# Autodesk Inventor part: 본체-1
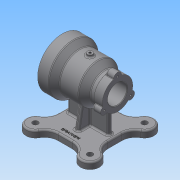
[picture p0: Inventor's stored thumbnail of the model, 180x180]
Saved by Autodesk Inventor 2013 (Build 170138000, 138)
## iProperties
Created: 2017-03
Part Number: 본체-1
Material: 일반
Document SubType Name: Modeling
Designer: Administrator
Density: 1 g/cm^3
Mass: 365.909 g
Surface Area: 842.375 cm^2
Volume: 365.909 cm^3
Author: Administrator
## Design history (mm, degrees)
sketch "스케치1"
  geometry: L1 (-50, 0)-(50, 0); L2 (-50, 35)-(-27, 35); L3 (-27, 35)-(-27, 26); L4 (-27, 26)-(20, 26); L5 (20, 26)-(20, 17.5); L6 (20, 17.5)-(50, 17.5); L7 (50, 17.5)-(50, 27.5); L8 (50, 27.5)-(35, 27.5); L9 (15, 36)-(-19, 36); L10 (-19, 36)-(-30, 45); L11 (-30, 45)-(-50, 45); L12 (-50, 45)-(-50, 35); L13 (15, 36)-(27, 26.182); L14 (27, 26.182)-(35, 26.182); L15 (35, 26.182)-(35, 27.5); 2 further points
  constraints: 30 end point, 9 parallel, 3 perpendicular, 2 vertical alignment, 1 coincident, 1 horizontal, 1 midpoint, 1 vertical
  dimensions: "d0" = 100 distance of L1.start L1.end; "d2" = 20 distance of L10.end L11.end; "d3" = 31 distance from line of L9.end L12; "d6" = 65 distance from line of L9.start L12; "d8" = 70 diameter of L2 L1; "d9" = 52 diameter of L4 L1; "d10" = 35 diameter of L6 L1; "d11" = 23 distance of L2.start L2.end; "d12" = 47 distance of L3.end L4.end; "d13" = 90 diameter of L11 L1; "d17" = 55 diameter of L8 L1; "d18" = 72 diameter of L9 L1; "d19" = 23 distance from line of L13.end L7; "d20" = 15 distance of L7.end L8.end
revolve "회전1" sketch "스케치1" stored, may be unused: angle "d21" = 90 deg
node "작업 평면1"
sketch "스케치2"
  geometry: L1 (-45, 45)-(45, 45); L2 (45, 45)-(45, -45); L3 (45, -45)-(-45, -45); L4 (-45, -45)-(-45, 45); L5 (-45, 45)-(45, -45); L6 (45, 45)-(-45, -45); L7 (-45, -33.103)-(-45, 33.103); L8 (45, 33.103)-(45, -33.103); L9 (-33.103, 45)-(33.103, 45); L10 (-33.103, -45)-(33.103, -45); A1 r 70 centre (0, 0) between (-49.497, 49.497) and (49.497, 49.497); A2 r 17 centre (-49.497, 49.497) between (-45, 33.103) and (-33.103, 45); A3 r 17 centre (49.497, 49.497) between (45, 33.103) and (33.103, 45); A4 r 17 centre (-49.497, -49.497) between (-45, -33.103) and (-33.103, -45); A5 r 17 centre (49.497, -49.497) between (45, -33.103) and (33.103, -45); 3 further points
  constraints: 20 end point, 12 point on circle, 8 point on line, 5 centre point, 5 coincident, 3 equal radius, 2 horizontal alignment, 2 midpoint, 2 parallel, 2 perpendicular, 2 vertical alignment, 1 horizontal
  dimensions: "d23" = 140 diameter of A1; "d26" = 90 distance of L1.start L1.end; "d27" = 90 deg dimension on point (0, 0) A1.start point (-49.497, -49.497); "d28" = 34 diameter of A2
extrude "돌출1" join sketch "스케치2" distance "d29" = 12; taper "d30" = 0 deg
fillet "모깎기1" dims "d35" = 25
node "작업 평면2"
sketch "스케치5"
  geometry: C1 r 5 at (0, 0); 1 further point
  constraints: 1 centre point, 1 coincident
  dimensions: "d37" = 10 diameter of C1
extrude "돌출2" join sketch "스케치5" stored distance "d39" = 74; taper "d40" = 0 deg
sketch "스케치6"
  geometry: C1 r 5 at (0, 0) reference; 1 further point
  constraints: 1 coincident
hole "구멍1" sketch "스케치6" at (0, 0) diameter "d41" = 4.134; stored, may be unused: countersink angle "d45" = 90 deg, drill point angle "d47" = 118 deg; dims "d42" = 6, "d43" = 4, "d44" = 2, "d46" = 8
sketch "스케치8"
  geometry: C1 r 5 at (-49.497, 49.497); C2 r 5 at (49.497, 49.497); C3 r 5 at (-49.497, -49.497); C4 r 5 at (49.497, -49.497); A1 r 17 centre (-49.497, 49.497) between (-34.661, 57.796) and (-57.796, 34.661) reference; A2 r 17 centre (-49.497, -49.497) between (-57.796, -34.661) and (-34.661, -57.796) reference; A3 r 17 centre (49.497, -49.497) between (34.661, -57.796) and (57.796, -34.661) reference; A4 r 17 centre (49.497, 49.497) between (57.796, 34.661) and (34.661, 57.796) reference; 1 further point
  constraints: 4 centre point, 4 coincident, 3 equal radius
  dimensions: "d60" = 10 diameter of C1
extrude "돌출3" cut sketch "스케치8" stored distance "d62" = 74; taper "d63" = 0 deg
sketch "스케치9"
  geometry: C1 r 17.5 at (0, 0) reference; A1 r 27.5 centre (0, 0) between (-27.5, 0) and (-26.609, -6.943) reference; A2 r 7 centre (-27.5, 0) between (-26.609, 6.943) and (-26.609, -6.943)
  constraints: 5 point on circle, 1 centre point, 1 horizontal alignment
  dimensions: "d64" = 14 diameter of A2
extrude "돌출4" join sketch "스케치9" distance "d66" = 15; taper "d67" = 0 deg
sketch "스케치10"
  geometry: A1 r 7 centre (0, 0) between (0.891, 6.943) and (0.891, -6.943) reference; 1 further point
  constraints: 1 coincident
hole "구멍3" sketch "스케치10" at (0, 0) diameter "d68" = 3.242; stored, may be unused: countersink angle "d72" = 90 deg, drill point angle "d74" = 118 deg; dims "d69" = 9, "d70" = 4, "d71" = 2, "d73" = 11
sketch "스케치11"
  geometry: L1 (12.842, -70)-(-12.842, -70) reference; L2 (-12.842, -70)-(-34.661, -70) reference; L3 (-34.661, -70)-(-66.497, -70) reference; L4 (34.661, -70)-(12.842, -70) reference; L5 (66.497, -70)-(34.661, -70) reference; L6 (-18.14, -31.096)-(-25, -70); L7 (0, 0)-(0, -70); L8 (0, -36)-(0, -70); A1 r 36 centre (0, 0) between (-18.14, -31.096) and (0, -36) reference; 3 further points
  constraints: 6 end point, 2 point on circle, 2 point on line, 1 collinear, 1 midpoint
  dimensions: "d78" = 100 deg angle of L6 L3; "d79" = 25 horizontal distance of L6.end point (0, 0)
extrude "돌출5" join sketch "스케치11" stored distance "d80" = 8; taper "d81" = 0 deg
chamfer "모따기1" distance "d86" = 1; stored, may be unused: second distance "d87" = 2, angle "d88" = 45 deg
fillet "모깎기3" dims "d89" = 3
sketch "스케치13"
  geometry: L1 (29.226, -44.367)-(19.774, -36.633) reference; L2 (18, -36)-(-14, -36) reference; L3 (4, -70)-(4, -31.096) reference; L4 (19.774, -36.633)-(18, -36) reference; L5 (50, -45)-(31, -45) reference; L6 (37.279, -70)-(12.842, -70) reference; L7 (37.279, -70)-(63.497, -70) reference; L8 (31, -45)-(29.226, -44.367) reference; L9 (37, -45)-(37, -70); 2 further points
  constraints: 2 end point, 2 point on line, 1 vertical
  dimensions: "d94" = 37 distance from line of L9 point (0, 0)
feature "리브1" sketch "스케치13" dims "d95" = 1, "d96" = 8, "d97" = 0, "d98" = 0, "d99" = 1, "d100" = 1
fillet "모깎기4" dims "d101" = 3
fillet "모깎기5" dims "d102" = 3
fillet "모깎기6" dims "d103" = 3
sketch "스케치14" dims "d104" = 80
  geometry: C1 r 36 at (0, 0) reference; 1 further point
  constraints: 2 horizontal alignment, 2 other
hole "구멍4" sketch "스케치14" at (40, 0) diameter "d106" = 3.242; stored, may be unused: countersink angle "d110" = 90 deg, drill point angle "d112" = 118 deg; dims "d107" = 9, "d108" = 4, "d109" = 2, "d111" = 11
fillet "모깎기7" dims "d116" = 3
fillet "모깎기8" dims "d117" = 1, "d118" = 3
fillet "모깎기9" dims "d119" = 3
sketch "스케치15"
  geometry: L1 (45, -12.842)-(45, 12.842) reference; 2 further points
  constraints: 1 other
  dimensions: "d120" = 35 distance of point (0, -35) point (0, 0); "d121" = 45 distance from line of point (0, -35) L1
feature "엠보싱1" sketch "스케치15" dims "d0" = 100, "d2" = 20, "d3" = 31, "d6" = 65, "d8" = 70, "d9" = 52, "d10" = 35, "d11" = 23, "d12" = 47, "d13" = 90, "d17" = 55, "d18" = 72, "d19" = 23, "d20" = 15, "d23" = 140, "d26" = 90, "d27" = 90 deg, "d28" = 34, "d122" = 0.5, "d123" = 0
fillet "모깎기10" dims "d124" = 1
node "솔리드1"
pattern_circular "원형 패턴2" dims angle "d76" = 360 deg
mirror "대칭1"
mirror "대칭2"
pattern_circular "원형 패턴3" dims angle "d114" = 360 deg
other parameters: "d22" = -82
